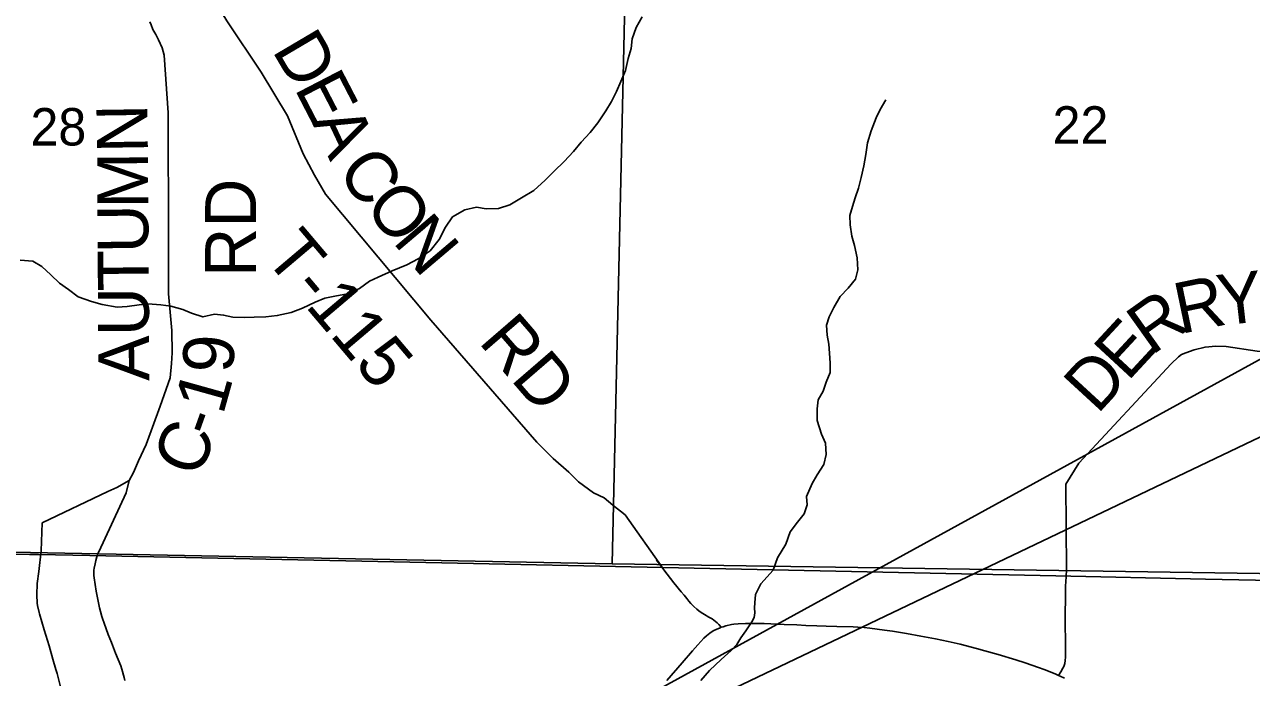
# Model space of a CAD drawing. Extents: x 0 to 34, y 0 to 22.
# Drawn here: x 4.921 to 6.292, y 17.833 to 18.562 of the extents above; entities that cross this region are included whole.
import ezdxf

# ---------------------------------------------------------------- set-up
doc = ezdxf.new("R2010")
doc.units = 0
for name, color, linetype in [('GM_X_Corporation', 7, 'Continuous'), ('GM_X_County_Road_Text', 7, 'Continuous'), ('GM_X_Interchange_Ramps', 7, 'Continuous'), ('GM_X_Interstate_Route', 7, 'Continuous'), ('GM_X_Major_Lake', 7, 'Continuous'), ('GM_X_Minor_Lake', 7, 'Continuous'), ('GM_X_Section', 7, 'Continuous'), ('GM_X_Township_Road_Text', 7, 'Continuous'), ('GM_X_Unincorporated', 7, 'Continuous'), ('SH_Cut_Line', 7, 'Continuous'), ('SH_Data', 7, 'Continuous')]:
    doc.layers.add(name, color=color, linetype=linetype)

msp = doc.modelspace()

# ---------------------------------------------------------------- linework, layer by layer
at = {"layer": 'GM_X_Corporation'}
msp.add_lwpolyline([(4.9398, 17.9742), (4.9408, 18.0054), (5.0141, 18.0404), (5.024, 18.0448), (5.038, 18.0529), (5.0429, 18.0617), (5.0485, 18.0748), (5.057, 18.0932), (5.0725, 18.1357), (5.0836, 18.1674), (5.0851, 18.1835), (5.0861, 18.1955), (5.0857, 18.2203), (5.082, 18.2613), (5.082, 18.3207), (5.0813, 18.4637), (5.077, 18.5279), (5.0746, 18.5361), (5.0708, 18.5449), (5.0676, 18.551), (5.0644, 18.5566), (5.0624, 18.5617), (5.061, 18.5652)], dxfattribs=at)
at = {"layer": 'GM_X_Interchange_Ramps'}
msp.add_lwpolyline([(6.6698, 20.9), (2.1, 20.9), (2.1, 17.9098), (2.4376, 17.9025), (2.6711, 17.8975), (2.9484, 17.8857), (3.604, 17.8577), (3.7063, 17.8588), (3.7128, 17.9822), (4.1825, 17.9744), (4.4481, 17.9728), (4.5919, 17.9719), (4.9267, 17.9702), (4.9368, 17.9702), (4.994, 17.969), (5.3871, 17.9608), (5.6339, 17.9555), (6.0729, 17.9463), (6.24, 17.9427), (6.5943, 17.9356), (6.6079, 18.3189), (6.6258, 18.9603), (6.6304, 19.2166), (6.6438, 19.9593)], close=True, dxfattribs=at)
for points in [[(6.5883, 17.471), (6.5943, 17.9356), (6.24, 17.9427), (6.0729, 17.9463), (5.6339, 17.9555), (5.3871, 17.9608), (4.994, 17.969), (4.9368, 17.9702), (4.9267, 17.9702), (4.5919, 17.9719), (4.4481, 17.9728), (4.1825, 17.9744), (3.7128, 17.9822), (3.7063, 17.8588), (3.604, 17.8577), (2.9484, 17.8857), (2.6711, 17.8975), (2.4376, 17.9025), (2.1, 17.9098), (2.1, 14.1)], [(5.6386, 17.8294), (5.6555, 17.849), (5.6672, 17.8627), (5.673, 17.8693), (5.6763, 17.8729), (5.68, 17.8767), (5.6827, 17.8791), (5.6867, 17.8823), (5.6904, 17.8848), (5.6943, 17.8867), (5.6972, 17.888), (5.6993, 17.8888), (5.7013, 17.8895), (5.7044, 17.8904), (5.7108, 17.8919), (5.7134, 17.8923), (5.7183, 17.8926), (5.7265, 17.8929), (5.7356, 17.893), (5.7472, 17.8929), (5.7697, 17.8921), (5.7838, 17.8915), (5.7936, 17.891), (5.806, 17.8904), (5.8166, 17.89), (5.8283, 17.8897), (5.8467, 17.8893), (5.852, 17.8891), (5.8589, 17.8886), (5.8652, 17.8879), (5.8817, 17.8857), (5.8904, 17.8844), (5.9062, 17.8818), (5.9223, 17.8788), (5.9384, 17.8758), (5.9528, 17.8729), (5.9663, 17.8698), (5.9842, 17.8653), (5.9938, 17.8627), (6.0087, 17.8585), (6.0282, 17.8526), (6.0388, 17.8492), (6.0537, 17.844), (6.06, 17.8417), (6.0723, 17.8368), (6.0761, 17.8351), (6.0779, 17.8343), (6.0828, 17.8319)]]:
    msp.add_lwpolyline(points, dxfattribs=at)
at = {"layer": 'GM_X_Interstate_Route'}
for points in [[(5.119, 18.6126), (5.1469, 18.5663), (5.1854, 18.5091), (5.2146, 18.4601), (5.2322, 18.4179), (5.2451, 18.394), (5.2571, 18.3728), (5.375, 18.2318), (5.4932, 18.0957), (5.5117, 18.0772), (5.5291, 18.0622), (5.5398, 18.0515), (5.5566, 18.0389), (5.5686, 18.0335), (5.5781, 18.0252), (5.5919, 18.0144), (5.6341, 17.955)], [(6.0849, 17.9534), (6.0841, 18.0487), (6.0987, 18.072), (6.2019, 18.1833), (6.2101, 18.191), (6.2132, 18.1934), (6.2181, 18.1956), (6.2275, 18.1986), (6.2397, 18.2018), (6.2519, 18.2028), (6.2633, 18.2026), (6.2977, 18.1972), (6.3058, 18.1968), (6.3122, 18.1974), (6.385, 18.2185), (6.3971, 18.2236), (6.4344, 18.2459), (6.4488, 18.2538), (6.4856, 18.2602), (6.5841, 18.3055), (6.5876, 18.3071), (6.5903, 18.3084), (6.5946, 18.3108)], [(5.038, 18.0529), (5.0344, 18.0389), (5.004, 17.9732)], [(5.6993, 17.8888), (5.6964, 17.892), (5.6947, 17.8937), (5.6908, 17.8969), (5.689, 17.8982), (5.6854, 17.9003), (5.6807, 17.903), (5.6767, 17.9054), (5.6744, 17.9071), (5.672, 17.9089), (5.6685, 17.9119), (5.6654, 17.9153), (5.6632, 17.918), (5.6607, 17.921), (5.6578, 17.9246), (5.6545, 17.9286), (5.6464, 17.9384), (5.6352, 17.9531), (5.6295, 17.9603), (5.6269, 17.9637)], [(6.0761, 17.8351), (6.0787, 17.8391), (6.0809, 17.843), (6.0819, 17.8452), (6.0829, 17.8485), (6.0835, 17.8519), (6.0837, 17.8554), (6.0839, 17.8606), (6.0836, 17.9046), (6.0837, 17.9206), (6.0839, 17.9349), (6.0844, 17.9451), (6.0849, 17.9534)]]:
    msp.add_lwpolyline(points, dxfattribs=at)
at = {"layer": 'GM_X_Minor_Lake'}
for points in [[(4.5812, 18.9996), (5.6006, 18.9822), (5.5776, 17.9596), (4.5642, 17.9795)], [(5.6006, 18.9822), (6.6311, 18.9612), (6.6, 17.9446), (5.5776, 17.9596)]]:
    msp.add_lwpolyline(points, close=True, dxfattribs=at)
at = {"layer": 'GM_X_Township_Road_Text'}
for points in [[(4.9161, 18.2991), (4.9302, 18.298), (4.9405, 18.2917), (4.9504, 18.2827), (4.96, 18.2732), (4.9703, 18.2661), (4.981, 18.2579), (4.9959, 18.2527), (5.0077, 18.2494), (5.0244, 18.2465), (5.0358, 18.2473), (5.0491, 18.2489), (5.0586, 18.2502), (5.0734, 18.2492), (5.0844, 18.2477), (5.0978, 18.2437), (5.1077, 18.2396), (5.1202, 18.2355), (5.1331, 18.2386), (5.1434, 18.2376), (5.1537, 18.2354), (5.167, 18.2348), (5.1776, 18.2352), (5.1905, 18.2357), (5.2034, 18.237), (5.2189, 18.2405), (5.2314, 18.2452), (5.2458, 18.2521), (5.2564, 18.2564), (5.2678, 18.2588), (5.2818, 18.2615), (5.2951, 18.2673), (5.3064, 18.2754), (5.3162, 18.2801), (5.3317, 18.287), (5.348, 18.2936), (5.3609, 18.3006), (5.3741, 18.3094), (5.3842, 18.322), (5.3913, 18.3357), (5.3992, 18.3472), (5.4128, 18.3553), (5.4257, 18.358), (5.4367, 18.3562), (5.4504, 18.3567), (5.4633, 18.3606), (5.4761, 18.3687), (5.4898, 18.3768), (5.5026, 18.3883), (5.5127, 18.3983), (5.5237, 18.409), (5.5342, 18.4205), (5.5429, 18.4308), (5.553, 18.4415), (5.5613, 18.4522), (5.5703, 18.4656), (5.5767, 18.4762), (5.5823, 18.4873), (5.5871, 18.4987), (5.5923, 18.5109), (5.5952, 18.5242), (5.5986, 18.5353), (5.5996, 18.5463), (5.6044, 18.5589), (5.6108, 18.5707)], [(5.7572, 17.9527), (5.7621, 17.9665), (5.7715, 17.9817), (5.7763, 17.9954), (5.7846, 18.0061), (5.7917, 18.0157), (5.7954, 18.0256), (5.7946, 18.0351), (5.8009, 18.0495), (5.8065, 18.0591), (5.8137, 18.0705), (5.8166, 18.0819), (5.8157, 18.0945), (5.8111, 18.1047), (5.8064, 18.1198), (5.8063, 18.1327), (5.8074, 18.143), (5.813, 18.1525), (5.8163, 18.1628), (5.8208, 18.1735), (5.8211, 18.1837), (5.8202, 18.1951), (5.8194, 18.205), (5.8174, 18.2152), (5.8169, 18.2262), (5.8199, 18.2357), (5.8251, 18.246), (5.8322, 18.2582), (5.8412, 18.2678), (5.8491, 18.2777), (5.8517, 18.288), (5.8512, 18.3017), (5.8481, 18.3153), (5.8453, 18.3259), (5.8433, 18.3384), (5.8428, 18.3487), (5.8458, 18.359), (5.8488, 18.3685), (5.8525, 18.3795), (5.8554, 18.3913), (5.8587, 18.4042), (5.8609, 18.4168), (5.8627, 18.4301), (5.8667, 18.4434), (5.8723, 18.4579), (5.8768, 18.4674), (5.8832, 18.4781)], [(5.6763, 17.8293), (5.686, 17.8405), (5.6991, 17.8529), (5.7103, 17.863), (5.7167, 17.8695), (5.7211, 17.8772), (5.7267, 17.8849), (5.7333, 17.8949), (5.7359, 17.8999), (5.7366, 17.9049), (5.7365, 17.9106), (5.7368, 17.9163), (5.7375, 17.9255), (5.7436, 17.9372), (5.7572, 17.9527)]]:
    msp.add_lwpolyline(points, dxfattribs=at)
at = {"layer": 'GM_X_Unincorporated'}
for points in [[(4.9621, 17.8195), (4.9575, 17.8372), (4.9561, 17.8417), (4.9528, 17.8532), (4.9484, 17.8681), (4.9429, 17.886), (4.9376, 17.9039), (4.9372, 17.9055), (4.9355, 17.9132), (4.9352, 17.9159), (4.9348, 17.9251), (4.9351, 17.9376), (4.9369, 17.9511), (4.9398, 17.9742)], [(5.033, 17.8295), (5.0322, 17.8329), (5.0299, 17.8419), (5.0287, 17.8456), (5.0227, 17.8599), (5.0181, 17.8719), (5.0146, 17.8807), (5.01, 17.8933), (5.0082, 17.8986), (5.0075, 17.901), (5.0058, 17.9066), (5.0047, 17.9106), (5.0021, 17.9237), (5.001, 17.9293), (4.9987, 17.9441), (4.9984, 17.9467), (4.9986, 17.9528), (4.9989, 17.9547), (4.9999, 17.9597), (5.0007, 17.9636), (5.0018, 17.9674), (5.0031, 17.9711), (5.004, 17.9732)]]:
    msp.add_lwpolyline(points, dxfattribs=at)
at = {"layer": 'SH_Cut_Line'}
for points in [[(8.9, 17.8921), (8.9, 20.9), (2.1, 20.9), (2.1, 17.9098), (2.4376, 17.9025), (2.6711, 17.8975), (2.9484, 17.8857), (3.604, 17.8577), (3.7063, 17.8588), (3.7128, 17.9822), (4.1825, 17.9744), (4.4481, 17.9728), (4.5919, 17.9719), (4.9267, 17.9702), (4.9368, 17.9702), (4.994, 17.969), (5.3871, 17.9608), (5.6339, 17.9555), (6.0729, 17.9463), (6.24, 17.9427), (6.5943, 17.9356), (7.6027, 17.9156), (8.3297, 17.9059), (8.5492, 17.9006)], [(2.1, 17.9098), (2.1, 14.1), (8.9, 14.1), (8.9, 17.8921), (8.5492, 17.9006), (8.3297, 17.9059), (7.6027, 17.9156), (6.5943, 17.9356), (6.24, 17.9427), (6.0729, 17.9463), (5.6339, 17.9555), (5.3871, 17.9608), (4.994, 17.969), (4.9368, 17.9702), (4.9267, 17.9702), (4.5919, 17.9719), (4.4481, 17.9728), (4.1825, 17.9744), (3.7128, 17.9822), (3.7063, 17.8588), (3.604, 17.8577), (2.9484, 17.8857), (2.6711, 17.8975), (2.4376, 17.9025)]]:
    msp.add_lwpolyline(points, close=True, dxfattribs=at)
at = {"layer": 'SH_Data'}
msp.add_lwpolyline([(9.2998, 19.834), (5.078, 17.5171), (9.2998, 19.5346)], close=True, dxfattribs=at)

# ---------------------------------------------------------------- texts
at = {"layer": 'GM_X_County_Road_Text'}
for s, p in [('28', (4.9277, 18.427)), ('22', (6.0694, 18.429))]:
    msp.add_text(s, height=0.04186, rotation=0, dxfattribs=at).set_placement(p)
at = {"layer": 'GM_X_Major_Lake'}
for s, height, rotation, p in [('N', 0.0568, 90.8927, (5.0589, 18.419)), ('M', 0.0568, 90.3293, (5.0593, 18.3567)), ('RD', 0.05682, 90, (5.1796, 18.2803)), ('U', 0.0568, 90.3169, (5.0595, 18.3067)), ('T', 0.0568, 90.3229, (5.0598, 18.2642)), ('U', 0.0568, 90.3169, (5.0601, 18.2142)), ('A', 0.0568, 90.3206, (5.0603, 18.1642)), ('9', 0.0568, 87.3888, (5.1541, 18.1722)), ('1', 0.0568, 74.3673, (5.1426, 18.1249)), ('C', 0.0568, 68.5626, (5.1158, 18.054)), ('-', 0.0568, 70.3299, (5.1334, 18.0989))]:
    msp.add_text(s, height=height, rotation=rotation, dxfattribs=at).set_placement(p)
at = {"layer": 'GM_X_Section'}
for s, height, rotation, p in [('D', 0.0568, 300.5596, (5.1968, 18.5335)), ('E', 0.0568, 297.4074, (5.2219, 18.4912)), ('A', 0.0568, 295.2486, (5.2412, 18.454)), ('C', 0.0568, 306.4909, (5.2687, 18.3983)), ('O', 0.0568, 310.2263, (5.299, 18.3576)), ('N', 0.0568, 310.2369, (5.3313, 18.3194)), ('T-115', 0.05682, 310.2363, (5.1874, 18.3024)), ('Y', 0.0568, 6.4979, (6.2564, 18.2256)), ('R', 0.0568, 11.7382, (6.212, 18.2163)), ('R', 0.0568, 35.4569, (6.1797, 18.1917)), ('RD', 0.05682, 310.8148, (5.4271, 18.2074)), ('E', 0.0568, 47.2036, (6.1531, 18.1625)), ('D', 0.0568, 47.3975, (6.1193, 18.1258))]:
    msp.add_text(s, height=height, rotation=rotation, dxfattribs=at).set_placement(p)

doc.saveas('drawing.dxf')
